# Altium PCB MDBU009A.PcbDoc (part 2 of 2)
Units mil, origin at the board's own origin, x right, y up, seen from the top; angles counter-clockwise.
Board outline 2000 x 3000 mil, 2 copper layers (Top Layer, Bottom Layer), stack 63.4 mil thick; 59 components, 52 nets, 252 pads, 189 vias.
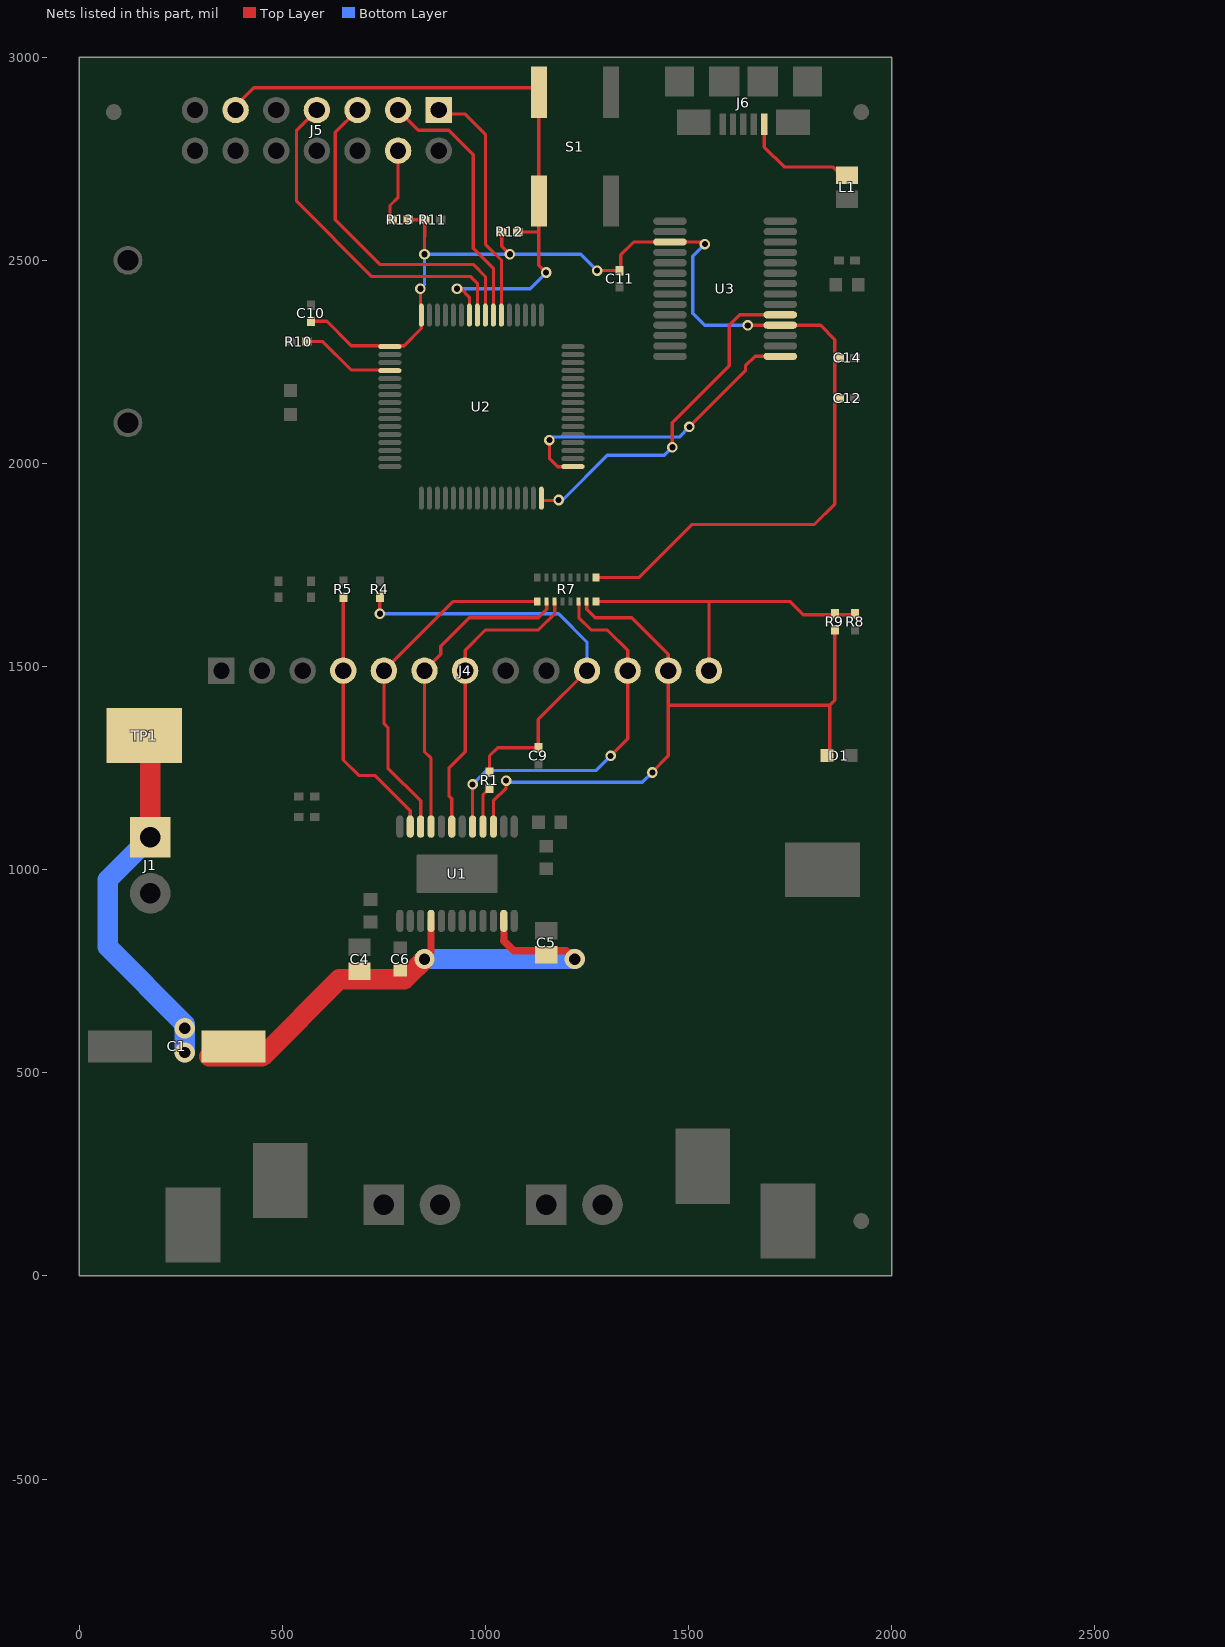
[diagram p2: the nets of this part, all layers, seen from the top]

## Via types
v1: diameter 26, hole 15, Top Layer to Bottom Layer, tented both sides, 177 vias
v2: diameter 19.68, hole 7.87, Top Layer to Bottom Layer, 8 vias
v3: diameter 50, hole 28, Top Layer to Bottom Layer, tented both sides, 4 vias

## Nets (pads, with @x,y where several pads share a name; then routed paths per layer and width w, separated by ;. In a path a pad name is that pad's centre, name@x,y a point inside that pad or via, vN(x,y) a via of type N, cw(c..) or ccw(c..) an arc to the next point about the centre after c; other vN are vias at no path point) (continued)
NetJ5_4: J5.4 R13.2 | length 178.3
  Top Layer w8: R13.2@765,2600 765,2635 785,2655 J5.4@785,2770
NFAULT: D1.2 J4.12 R7.7 R9.1 U1.15 | length 1784
  Top Layer w8: U1.15@1019.57,1102.2 1019.57,1169.57 1050.68,1200.68 v1(1050.68,1219.32) ; R7.7@1249.21,1658.5 1249.21,1640.79 1270,1620 1360,1620 1450,1530 J4.12@1450,1490 1450,1405 ; v1@1410,1240 1450,1280 1450,1405 ; D1.2@1847.8,1279.9 1847.8,1405 ; R9.1@1860,1588.35 1860,1417.2 1847.8,1405 ; 1450,1405 1847.8,1405
  Bottom Layer w8: v1(1050.68,1219.32) 1054.87,1215.13 1386.49,1215.13 v1(1410.68,1239.32)
NSLEEP: J4.11 R7.6 U1.17 | length 953.9
  Top Layer w8: U1.17@968.39,1102.2 v1(968.39,1210) v1@968.39,1218.39 ; R7.6@1230,1658.5 1230,1620 1260,1590 1300,1590 1350,1540 J4.11@1350,1490 1350,1322.1 v1(1307.9,1280)
  Bottom Layer w8: v1(968.39,1210) 1002.39,1244 1040.19,1244 1040.38,1244.19 1060.99,1244.19 1061.18,1244 1271.9,1244 v1(1307.9,1280)
RREF: R1.2 U1.16 | length 104.7
  Top Layer w8: U1.16@993.98,1102.2 993.98,1184.29 R1.2@1010,1200.31
RREF_R: C9.1 J4.10 R1.1 R4.1 | length 1046.1
  Top Layer w8: v1(740,1630) R4.1@740,1670.32 ; R1.1@1010,1241.65 1010,1280 1030,1300 1120,1300 ; C9.1@1130,1299.68 1130,1370 1140,1380 1250,1489.37 J4.10@1250,1490
  Bottom Layer w8: v1(740,1630) 1180,1630 1250,1560 J4.10@1250,1490
RST: J5.11 R12.1 S1.3 S1.4 U2.58 | length 1607.9
  Top Layer w8: J5.11@385,2880 430,2925 1125,2925 1131.42,2931.42 S1.3@1131.42,2913.86 S1.4@1131.42,2646.14 1131.42,2570 ; v1(930,2430) 940,2430 960.47,2409.53 U2.58@960.47,2365.39 ; R12.1@1079.68,2570 1131.42,2570 ; v1(1149.25,2470) 1131.42,2487.83 1131.42,2570
  Bottom Layer w8: v1(930,2430) 1110,2430 v1@1150,2470
RX: U2.32 U3.5 | length 859.5
  Top Layer w8: U2.32@1137.7,1909 v1@1167.38,1909 ; U2.32@1137.7,1929 U2.32@1138.7,1930 ; v1(1460,2040) 1460,2100 1600,2240 1600,2340 1626.02,2366.02 U3.5@1725.83,2366.02
  Bottom Layer w8: v1(1180,1910) 1190,1910 1300,2020 1440,2020 v1(1460,2040)
STATUS: R10.2 U2.4 | length 247.3
  Top Layer w8: R10.2@551.65,2300 600,2300 670,2230 U2.4@770,2230
STEP: J4.7 R7.3 U1.19 | length 745.3
  Top Layer w8: U1.19@917.2,1102.2 917.2,1175.14 910,1182.34 910,1250 950,1290 J4.7@950,1490 950,1540 1000,1590 1130,1590 1170.47,1630.47 R7.3@1170.47,1660.47
TCK: J5.7 U2.57 | length 827
  Top Layer w8: J5.7@585,2870 535,2820 535,2645 720,2460 964,2460 980.1,2443.9 U2.57@980.1,2391
TDI: J5.3 U2.55 | length 620.1
  Top Layer w8: J5.3@785,2870 834.99,2820 910,2820 970,2760 970,2530 1019.5,2480.5 U2.55@1019.5,2391
TDO: J5.1 U2.54 | length 590.9
  Top Layer w8: J5.1@865,2860 950,2860 1000,2810 1000,2539.98 1039.2,2500.78 U2.54@1039.2,2391
TMS: J5.5 U2.56 | length 789.7
  Top Layer w8: J5.5@685,2870 630,2815 630,2600 740,2490 970,2490 999.8,2460.2 U2.56@999.8,2391
TORQUE: J4.4 R5.1 U1.23 | length 657.9
  Top Layer w8: R5.1@650,1668.35 J4.4@650,1490 650,1270 688,1232 728,1232 814.84,1145.16 U1.23@814.84,1102.2
TX: U2.33 U3.1 | length 834
  Top Layer w8: v1(1157.5,2057.5) 1157.5,2012.5 1177.8,1992.2 U2.33@1220.9,1992.2 ; v1(1502,2090) 1640,2228 1640,2240 1663.66,2263.66 U3.1@1725.83,2263.66 ; U3.1@1693.6,2263.6 U3.1@1750,2263.6
  Bottom Layer w8: v1(1157.5,2057.5) 1165,2065 1477,2065 v1(1502,2090)
USM0: J4.6 R7.2 U1.21 | length 789.1
  Top Layer w8: U1.21@866.02,1102.2 866.02,1273.98 850,1290 J4.6@850,1490 890,1530 890,1550 960,1620 1130,1620 1150.79,1640.79 R7.2@1150.79,1660.47
USM1: J4.5 R7.1 U1.22 | length 873.5
  Top Layer w8: U1.22@840.43,1102.2 840.43,1169.57 760,1250 760,1350 750,1360 J4.5@750,1490 920,1660 1127.18,1660 R7.1@1127.66,1660.47
V3P3: C10.1 C11.1 C12.1 C14.1 R7.9 R11.1 R12.2 R13.1 U2.1 U2.64 U3.4 U3.17 | length 3156.9
  Top Layer w8: C10.1@570,2350 610,2350 670,2290 800,2290 842.2,2332.2 842.2,2371 840,2373.2 v1(840,2430) ; R13.1@810,2600 R11.1@850.32,2600 v1(850,2515) ; R12.2@1040.31,2570 1040,2569.69 1040,2535 v1(1060,2515) ; R7.9@1272.34,1719.53 1378.26,1719.53 1508.73,1850 1810,1850 1860,1900 1860,2305 1825,2340 U3.4@1750,2340 ; v1(1275,2474.68) C11.1@1330,2474.68 ; C11.1@1333.32,2478.32 1333.32,2513.32 1365.2,2545.2 1510,2545.2 ; U3.17@1454.17,2545.16 1534.84,2545.16 v1(1540,2540) ; v1@1655,2340 1655.43,2340.43 U3.4@1725.83,2340.43 ; U3.4@1685.4,2340.4 U3.4@1738.9,2340.4
  Bottom Layer w8: v1(840,2430) 850,2440 v1(850,2515) v1(1060,2515) 1234.68,2515 v1(1275,2474.68) ; v1(1540,2540) 1510,2510 1510,2370 1540,2340 v1@1655,2340
  other v1: 1645.72,2340
V3P3R: J4.13 R7.8 R8.2 R9.2 | length 821
  Top Layer w8: R7.8@1272.34,1660 1550,1660 ; J4.13@1550,1490 1550,1660 ; R8.2@1910,1627.72 1782.28,1627.72 1750,1660 1550,1660
VBUS: J6.1 L1.2 | length 293.7
  Top Layer w8: J6.1@1686.18,2840 1686.18,2778.82 1735,2730 1854.56,2730 1875.03,2709.53 L1.2@1890,2709.53
VM: C1.1 C4.2 C5.2 C6.1 J1.1 TP1.1 U1.4 U1.11 | length 2286.3
  Top Layer w17: v3@866.02,796.02 U1.4@866.02,877.8 ; 1045.16,824.84 U1.11@1045.16,873.86
  Top Layer w18: v3(850,780) v3@866.02,796.02 ; 1045.16,824.84 1069.68,800.32 1199.68,800.32 v3(1220,780)
  Top Layer w50: TP1.1@140,1360 175,1325 J1.1@175,1080 ; C1.1@320,540 450,540 640,730 800,730 ; 804.83,734.66 v3(850,780)
  Bottom Layer w50: J1.1@175,1080 70,975 70,810 260,620 v3(260,550) ; v3(850,780) v3(1220,780)
  other v3: 260,610
pads on no net: FID1.1 FID2.1 FID3.1 J5.6 J5.8 J5.10 J5.12 J5.13 J5.14 J6.4 U2.2 U2.3 U2.7 U2.8 U2.9 U2.12 U2.13 U2.14 U2.15 U2.16 U2.17 U2.18 U2.19 U2.20 U2.21 U2.22 U2.27 U2.28 U2.29 U2.30 U2.31 U2.34 U2.35 U2.36 U2.39 U2.40 U2.43 U2.44 U2.45 U2.46 U2.47 U2.48 U2.49 U2.50 U2.51 U2.52 U2.53 U2.59 U2.60 U2.61 U3.2 U3.3 U3.6 U3.8 U3.9 U3.10 U3.11 U3.12 U3.13 U3.14 U3.19 U3.22 U3.23 U3.24 U3.27 U3.28
copper on no net: | length 277.2
  Top Layer w8: 2450,-780 2727.18,-780

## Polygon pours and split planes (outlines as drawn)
GND on Top Layer "Top Layer-GND" (solid, remove dead copper, pour order 12): -4.31,-2.25 -4.31,2997.75 1995.69,2997.75 1995.69,-2.25
GND on Bottom Layer "Bottom Layer-GND" (solid, remove dead copper, pour order 8): 0,-5 0,2995 2000,2995 2000,-5

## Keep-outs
Keep-Out Layer:
  lines w10: -5,-5 2005,-5 2005,3005 -5,3005 -5,-5
  text ".Layer_Name" at 577,-858.49 h60

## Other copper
Top Layer:
  region net GND: 863.77,2332.57 883.47,2332.57 883.47,2302.57 863.77,2302.57
  region net GND: 1140,2290 1198.95,2348.95 1211.05,2348.95 1230,2330 1220,2320 1202.47,2319.14 1195.81,2318.48 1157.32,2280
  region net GND: 790,1960 820,1990 840,1970 810,1940
  region net GND: 1130,830 1070,830 1070,910 1130,910
  region net BOUT1: 1011,807 1011,778 1025,764 1046,785 1028,803 1028,807 1027,808 1012,808
  region net BOUT2: 972,797 972,823 969,826 976,842 1002,816 1002,797
  region net AOUT2: 927,810 927,836 935,844 951,844 952,842 952,822 956,818 957,814 957,810
  region net AOUT1: 885,807 884,826 885,834 899,834 899,833 915,817 915,807
  region net VM: 400,530 470,590 520,640 230,640 230,540 240,520 370,520
  region net GND: 1380,2345 1535,2345 1535,2314.32 1530.68,2310 1380,2310
  text ".Layer_Name" at 577,-858.49 h60
Bottom Layer:
  text ".Layer_Name" at 577,-858.49 h60

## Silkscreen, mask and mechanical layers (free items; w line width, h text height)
Top Overlay:
  circle w10: c740,827.88 r10
  lines w7: 630,670 1280,670 1280,1180 1178.12,1180 630,1180 630,670
  lines w8: 150,1690 460,1690 ; 780,1690 1100,1690 ; 1320,1690 1790,1690
  text "GND" at 70,2560 h40
  text "MCU Reset" at 1095,2515 h30
  text "Status" at 420,2020 h30
  text ".PRJ_Number" at 1430,1820 h40
  text ".PCB_Rev" at 1430,1730 h40
  text "DRV8885EVM" at 1430,1630 h40
  text "VM" at 60,1430 h40
  text "GND" at 340,1410 h30 r270
  text "DVDD" at 440,1410 h30 r270
  text "DECAY_R" at 540,1410 h30 r270
  text "TORQUE" at 640,1410 h30 r270
  text "USM1" at 740,1410 h30 r270
  text "USM0" at 840,1410 h30 r270
  text "STEP" at 935,1410 h30 r270
  text "ENABLE" at 1040,1410 h30 r270
  text "DIR" at 1140,1410 h30 r270
  text "RREF_R" at 1235,1410 h30 r270
  text "nSLEEP" at 1335,1410 h30 r270
  text "nFAULT" at 1440,1410 h30 r270
  text "V3P3R" at 1535,1410 h30 r270
  text "nFAULT" at 1755,1340 h30
  text "VM" at 320,1060 h40
  text "GND" at 320,930 h40
  text "GND" at 1790,820 h40
  text "DRV8885" at 800,610 h40
  text "BOUT1" at 1465,400 h30
  text "AOUT1" at 425,360 h30
  text "AOUT1" at 630,320 h30
  text "AOUT2" at 870,320 h30
  text "BOUT2" at 1030,320 h30
  text "BOUT1" at 1270,320 h30
  text "BOUT2" at 1670,265 h30
  text "AOUT2" at 205,250 h30
  text ".Layer_Name" at 577,-858.49 h60
Bottom Overlay:
  text ".Layer_Name" at 577,-858.49 h60
Top Paste:
  text ".Layer_Name" at 577,-858.49 h60
Bottom Paste:
  text ".Layer_Name" at 577,-858.49 h60
Top Solder:
  text ".Layer_Name" at 577,-858.49 h60
  text ".Layer_Name" at 577,-858.49 h60
Bottom Solder:
  text ".Layer_Name" at 577,-858.49 h60
Drill Guide:
  text ".Layer_Name" at 577,-858.49 h60
M1 Board Outline:
  the board outline again, w10
  text ".Layer_Name" at 577,-858.49 h60
M2 Board Dimensions:
  rectangle: 0,-275 125,-150
  rectangle: 125,-400 500,-275
  lines w7: 0,-275 1000,-275 ; 125,-400 125,-150 ; 250,-400 250,-150 ; 500,-400 500,-150 ; 750,-400 750,-150 ; 0,-400 1000,-400 1000,-150 0,-150 0,-400
  text ".Layer_Name" at 577,-858.49 h60
M3 3D STEP Top:
  text ".Layer_Name" at 577,-858.49 h60
M4 3D STEP Bottom:
  text ".Layer_Name" at 577,-858.49 h60
M5 Assembly Top:
  lines w10: -292,-930.17 6308,-930.17 ; -292,-726.83 6310,-726.83 ; -292,-523.5 -292,-1133.5 3713,-1133.5 6310,-1133.5 6310,-523.5 -291.5,-523.5 -291.5,-1133.5 1284,-1133.5 ; 2173,-1133.5 2173,-523.5 ; 3440,-726.83 3440,-523.5 ; 4280,-726.83 4280,-523.5 ; 4902,-1140 4902,-937.17
  text "COMPONENTS MARKED 'DNP' SHOULD NOT BE POPULATED." at 1153.5,-318.5 h60
  text "ASSEMBLY VARIANT:" at 1153,-434 h60
  text ".VariantName" at 2189,-434 h60
  text "PCB VIEWED FROM TOP SIDE" at -228.5,-655.67 h60
  text "BOARD #:" at 2248,-655.67 h60
  text ".PRJ_Number" at 2793.5,-655.67 h60
  text "REV:" at 3638,-655.67 h60
  text ".PCB_Rev" at 3929.5,-655.67 h60
  text "SVN REV:" at 4476,-655.67 h60
  text ".VersionControl_RevNumber" at 4982,-655.67 h60
  text "TID #:" at 2248,-859 h60
  text ".TID" at 2793.5,-859 h60
  text "PLOT NAME =" at -228.5,-1064.34 h60
  text ".plot_File_Name" at 577,-1064.34 h60
  text "GENERATED    :" at 2250,-1064.34 h60
  text ".Print_Date" at 3119.5,-1064.34 h60
  text ".Print_Time" at 3848.5,-1064.34 h60
  text "TEXAS INSTRUMENTS" at 5113,-1064.34 h60
M6 Assembly Bottom:
  lines w10: -292.5,-727.33 6309.5,-727.33 ; -290.5,-930.67 6309.5,-930.67 ; 1115.5,-1140.5 1115.5,-937.67 ; 1737.5,-727.33 1737.5,-524 ; 2577.5,-727.33 2577.5,-524 ; 3844.5,-1134 3844.5,-524 ; 4733.5,-1134 6309,-1134 6309,-524 -292.5,-524 -292.5,-1134 2304.5,-1134 6309.5,-1134 6309.5,-524
  text "COMPONENTS MARKED 'DNP' SHOULD NOT BE POPULATED." at 6102,-318 h60
  text ".VariantName" at 5058,-434 h60
  text "ASSEMBLY VARIANT:" at 6097,-434 h60
  text ".VersionControl_RevNumber" at 1035.5,-656.17 h60
  text "SVN REV:" at 1541.5,-656.17 h60
  text ".PCB_Rev" at 2088,-656.17 h60
  text "REV:" at 2379.5,-656.17 h60
  text ".PRJ_Number" at 3224,-656.17 h60
  text "BOARD #:" at 3769.5,-656.17 h60
  text "PCB VIEWED FROM BOTTOM SIDE" at 6246,-656.17 h60
  text ".TID" at 3224,-859.5 h60
  text "TID #:" at 3769.5,-859.5 h60
  text "TEXAS INSTRUMENTS" at 904.5,-1064.84 h60
  text ".Print_Time" at 2169,-1064.84 h60
  text ".Print_Date" at 2898,-1064.84 h60
  text "GENERATED    :" at 3767.5,-1064.84 h60
  text ".plot_File_Name" at 5440.5,-1064.84 h60
  text "PLOT NAME =" at 6246,-1064.84 h60
M9 Title Sheet:
  drawing of 57 lines, arcs and shapes, not listed
  text "1" at 739.84,8036.5 h70
  text "2" at 3235.5,8036.5 h70
  text "3" at 5724.84,8036.5 h70
  text "4" at 8231.51,8036.5 h70
  text "5" at 10730.5,8036.5 h70
  text "6" at 13235.5,8036.5 h70
  text "A" at -416.5,6893.5 h70
  text "A" at 14383.5,6893.5 h70
  text "B" at -416.5,4513.5 h70
  text "B" at 14383.5,4513.5 h70
  text "C" at -416.5,2138.5 h70
  text "C" at 14383.5,2138.5 h70
  text "PROJECT TITLE:" at 11343.5,277.5 h45
  text ".PRJ_Title" at 11393.5,144.17 h70
  text "DESIGNED FOR:" at 11343.5,-23.5 h45
  text ".PRJ_Customer" at 11393.5,-163.5 h70
  text "D" at -416.5,-231.5 h70
  text "D" at 14383.5,-231.5 h70
  text "FILE NAME:" at 11343.5,-323.5 h45
  text ".PCB_File_Name_No_Path" at 11393.5,-443.5 h70
  text "Texas Instruments (TI) and/or its licensors do not warrant the accuracy or completeness of this specification" at 6374,-605.34 h45
  text "ENGINEER:" at 11343.5,-613.5 h45
  text "LAYOUT BY:" at 12848.5,-613.5 h45
  text "or any information contained therein. TI and/or its licensors do not warrant that this design will meet" at 6329.01,-718 h45
  text ".PRJ_Engineer" at 11393.5,-768.49 h70
  text ".PCB_Layout" at 12899,-768.49 h70
  text "the specifications, will be suitable for your application or fit for any particular purpose, or will operate in" at 6329.01,-830.67 h45
  text ".Layer_Name" at 577,-858.49 h60
  text "ALTIUM DESIGNER VERSION:" at 12848.5,-923.5 h45
  text "an implementation. TI and/or its licensors do not warrant that the design is production worthy. You should" at 6329.01,-943.33 h45
  text "completely validate and test your design implementation to confirm the system functionality for your application." at 6374,-1056 h45
  text ".print_Scale" at 11393.5,-1056.83 h70
  text ".Application_BuildNumber" at 12899,-1056.83 h70
  text "1" at 739.84,-1263.5 h70
  text "2" at 3235.5,-1263.5 h70
  text "3" at 5724.84,-1263.5 h70
  text "4" at 8231.51,-1263.5 h70
  text "5" at 10730.5,-1263.5 h70
  text "6" at 13235.5,-1263.5 h70
M10 Fab Notes:
  drawing of 185 lines, arcs and shapes, not listed
  text "DESIGN INFORMATION" at 12381.02,5910 h60
  text "MIN. TRACK WIDTH:" at 11736.46,5730 h60
  text "8" at 12832.7,5730 h60
  text "MIL" at 12987.46,5730 h60
  text "MIN. CLEARANCE:" at 11736.46,5598 h60
  text "0.2" at 12772.7,5598 h60
  text "mm" at 12987.46,5598 h60
  text "MIN. VIA PAD SIZE:" at 11736.46,5466 h60
  text "24" at 12802.71,5466 h60
  text "MIL" at 12987.46,5466 h60
  text "0.05mm (2MIL)" at 12431.46,5324.29 h60
  text "MINIMUM ANNULAR RING" at 11407.23,5320 h60
  text "EXTERNAL" at 13139.46,5320 h60
  text "PER" at 11607.23,5202 h60
  text "IPC-D-275 CLASS 2 LEVEL C" at 11827.23,5202 h60
  text "MIL, HOLES" at 13315.46,5089.71 h60
  text "+/-" at 12923,5089 h60
  text "+/-" at 13777,5089 h60
  text "REGISTRATION TOLERANCES:" at 11407.23,5084 h60
  text "METAL" at 12607,5084 h60
  text "5" at 13183.2,5084 h60
  text "3" at 14016.2,5084 h60
  text "MIL" at 14132.46,5084 h60
  text "MATERIAL:" at 11332.46,4874.54 h60
  text "FR-4 High Tg" at 12318.9,4734.21 h60
  text "FR-408" at 11753.46,4725.64 h60
  text "X" at 12165.46,4725.64 h60
  text "OTHER" at 13241.46,4725.64 h60
  text "62 MIL (1.6mm) +/-10%" at 12073.56,4562.92 h60
  text "THICKNESS:" at 11407.23,4558.64 h60
  text "X" at 11945.4,4558.64 h60
  text "OTHER" at 13358.46,4558.64 h60
  text "TOLERANCE:" at 11407.23,4400.64 h60
  text "X" at 12246.53,4400.64 h60
  text "ANSI IPC-6012 TYPE 3 CLASS 2" at 12433.48,4400.64 h60
  text "OTHER +/-" at 12433.46,4244.64 h60
  text "BOW & TWIST:" at 11407.23,4087.64 h60
  text "X" at 12246.53,4087.64 h60
  text "ANSI IPC-6012 TYPE 3 CLASS 2" at 12433.48,4087.64 h60
  text "OTHER +/-" at 12433.46,3929.13 h60
  text "DRILLING:" at 11332.46,3790.64 h60
  text "REFERENCE:" at 11407.23,3673.64 h60
  text "X" at 12055.46,3673.64 h60
  text "AS SHOWN" at 12242.46,3673.64 h60
  text "X" at 12956.46,3673.64 h60
  text "NC_DRILL FILES" at 13093.46,3673.64 h60
  text "PTH MIN COPPER THICKNESS:" at 11407.23,3515.64 h60
  text "X" at 12757.46,3515.64 h60
  text "1MIL" at 12894.46,3515.64 h60
  text "OTHER" at 13391.46,3515.64 h60
  text "BOARD FINISH:" at 11332.46,3356.64 h60
  text "SILKSCREEN:" at 11487.68,3238.64 h60
  text "X" at 12436.46,3238.64 h60
  text "TOP" at 12562.46,3238.64 h60
  text "X" at 12946.46,3238.64 h60
  text "BOTTOM" at 13073.46,3238.64 h60
  text "SILKSCREEN COLOR:" at 11487.68,3071.64 h60
  text "X" at 12435.42,3071.64 h60
  text "WHITE" at 12562.46,3071.64 h60
  text "OTHER" at 13073.46,3071.64 h60
  text "SOLDER RESIST COLOR:" at 11487.68,2901.64 h60
  text "X" at 12055.42,2742.44 h60
  text "GREEN" at 12182.46,2742.44 h60
  text "BLUE" at 12773.46,2742.44 h60
  text "OTHER" at 13311.46,2742.44 h60
  text "IMMERSION GOLD (ENIG)" at 12393.46,2553.92 h60
  text "ENEPIG" at 13731,2550.64 h60
  text "SURFACE FINISH:" at 11332.46,2549.64 h60
  text "X" at 12206.51,2549.64 h60
  text "IMM. TIN/SILVER OR EQUIV" at 11662,2392.64 h60
  text "OTHER" at 13093.46,2392.64 h60
  text "ARRAY/PANEL:" at 11332.46,2213.64 h60
  text "CUT AND TRIM PER MECH LAYER 1" at 12393.46,2209.35 h60
  text "N.C. ROUTE" at 12393.46,2057.64 h60
  text "X" at 13072.46,2057.64 h60
  text "V. SCORE" at 13259.46,2057.64 h60
  text "CERTIFICATION:" at 11332.46,1920.64 h60
  text "MATERIALS AND WORKMANSHIP FOR ALL PCBS" at 12057.46,1920.64 h60
  text "TO MEET OR EXCEED THE REQUIREMENTS OF:" at 12057.46,1822.64 h60
  text "X" at 11683.96,1686.13 h60
  text "ANSI IPC-A-600F CLASS ->" at 11822.96,1686.13 h60
  text "X" at 13462.02,1686.13 h60
  text "2" at 13580.96,1686.14 h60
  text "1" at 13265.96,1684.64 h60
  text "3" at 13934.96,1684.64 h60
  text "X" at 11686.02,1526.64 h60
  text "UL 94V-0" at 11822.96,1526.64 h60
  text "X" at 12498.02,1526.64 h60
  text "RoHS" at 12634.96,1526.64 h60
  text "OTHER" at 13279.36,1526.64 h60
  text "PER ORDER" at 13676.42,1526.64 h60
  text "ADDITIONAL REQUIREMENTS:" at 11332.46,1385.64 h60
  text "MICROSECTION:" at 11407.23,1270.64 h60
  text "YES" at 12312.96,1270.64 h60
  text "REQUIRED" at 13174.46,1114.49 h60
  text "BARE BOARD ELEC. TEST:" at 11407.23,1111.64 h60
  text "NONE" at 12712.96,1111.64 h60
  text "X" at 13047.46,1111.64 h60
  text "PER ORDER" at 13766.46,1111.64 h60
  text "MANUFACTURER'S UL:" at 11407.23,954.64 h60
  text "RAIL" at 12572.96,950.35 h60
  text "METAL" at 13064.77,950.35 h60
  text "X" at 13440,950 h60
  text "SILK" at 13576.46,950.35 h60
  text ".Layer_Name" at 577,-858.49 h60
M11 Gerber Information:
  lines w10: -292,-930.17 6308,-930.17 ; -292,-726.83 6310,-726.83 ; -292,-523.5 -292,-1133.5 3713,-1133.5 6310,-1133.5 6310,-523.5 -291.5,-523.5 -291.5,-1133.5 1284,-1133.5 ; 2173,-1133.5 2173,-523.5 ; 3440,-726.83 3440,-523.5 ; 4280,-726.83 4280,-523.5 ; 4902,-1140 4902,-937.17
  text "ALL ARTWORK VIEWED FROM TOP SIDE" at -228.5,-655.67 h60
  text "BOARD #:" at 2248,-655.67 h60
  text ".PRJ_Number" at 2793.5,-655.67 h60
  text "REV:" at 3638,-655.67 h60
  text ".PCB_Rev" at 3929.5,-655.67 h60
  text "SVN REV:" at 4476,-655.67 h60
  text ".VersionControl_RevNumber" at 4982,-655.67 h60
  text "LAYER NAME =" at -228.5,-858.49 h60
  text "TID #:" at 2248,-859 h60
  text ".TID" at 2793.5,-859 h60
  text "PLOT NAME =" at -228.5,-1064.34 h60
  text ".plot_File_Name" at 577,-1064.34 h60
  text "GENERATED    :" at 2250,-1064.34 h60
  text ".Print_Date" at 3119.5,-1064.34 h60
  text ".Print_Time" at 3848.5,-1064.34 h60
  text "TEXAS INSTRUMENTS" at 5113,-1064.34 h60
M12 Stackup:
  drawing of 165 lines, arcs and shapes, not listed
  text "Layer" at 9790,7830 h60
  text "Name" at 10199.91,7830 h60
  text "Material" at 11059.68,7830 h60
  text "Thickness" at 11919.45,7830 h60
  text "Constant" at 12569.28,7830 h60
  text "Board Layer Stack" at 13139.14,7830 h60
  text "1" at 9790,7710 h60
  text "Top Overlay" at 10199.91,7710 h60
  text "2" at 9790,7590 h60
  text "Top Solder" at 10199.91,7590 h60
  text "Solder Resist" at 11059.68,7590 h60
  text "0.40mil" at 11919.45,7590 h60
  text "3.5" at 12569.28,7590 h60
  text "3" at 9790,7470 h60
  text "Top Layer" at 10199.91,7470 h60
  text "Copper" at 11059.68,7470 h60
  text "2.10mil" at 11919.45,7470 h60
  text "4" at 9790,7350 h60
  text "Dielectric1" at 10199.91,7350 h60
  text "FR-4" at 11059.68,7350 h60
  text "59.20mil" at 11919.45,7350 h60
  text "4.8" at 12569.28,7350 h60
  text "5" at 9790,7230 h60
  text "Bottom Layer" at 10199.91,7230 h60
  text "Copper" at 11059.68,7230 h60
  text "2.10mil" at 11919.45,7230 h60
  text "6" at 9790,7110 h60
  text "Bottom Solder" at 10199.91,7110 h60
  text "Solder Resist" at 11059.68,7110 h60
  text "0.40mil" at 11919.45,7110 h60
  text "3.5" at 12569.28,7110 h60
  text ".Layer_Name" at 577,-858.49 h60
M13 Component Bodies Top:
  text ".Layer_Name" at 577,-858.49 h60
M14 Component Bodies Bottom:
  text ".Layer_Name" at 577,-858.49 h60
M15 Courtyards Top:
  text ".Layer_Name" at 577,-858.49 h60
M16 Courtyards Bottom:
  text ".Layer_Name" at 577,-858.49 h60
Drill Drawing:
  circle w1: c2592.8,2770.83 r24.91
  lines w1: 2567.89,2023.54 2592.8,1998.63 2617.71,2023.54 2592.8,2048.45 2567.89,2023.54 ; 2567.89,2148.09 2567.89,2160.54 2580.35,2173 2567.89,2185.45 2567.89,2197.91 2580.35,2197.91 2592.8,2185.45 2605.26,2197.91 2617.71,2197.91 2617.71,2185.45 2605.26,2173 2617.71,2160.54 2617.71,2148.09 2605.26,2148.09 2592.8,2160.54 2580.35,2148.09 2567.89,2148.09 ; 2567.89,2310 2580.35,2310 2580.35,2297.54 2605.26,2297.54 2605.26,2310 2617.71,2310 2617.71,2334.91 2605.26,2334.91 2605.26,2347.36 2580.35,2347.36 2580.35,2334.91 2567.89,2334.91 2567.89,2310 ; 2567.89,2459.46 2580.35,2459.46 2592.8,2447 2605.26,2459.46 2617.71,2459.46 2605.26,2471.91 2617.71,2484.37 2605.26,2484.37 2592.8,2496.82 2580.35,2484.37 2567.89,2484.37 2580.35,2471.91 2567.89,2459.46 ; 2567.89,2646.28 2617.71,2646.28 2592.8,2596.46 2567.89,2646.28
  lines w12: 2500,1953.79 4619.4,1953.79 ; 2500,2850.54 4619.4,2850.54 ; 2870.67,1804.33 2870.67,3000 ; 3227.78,1804.33 3227.78,3000 ; 3889.79,1804.33 3889.79,3000 ; 4174.14,1804.33 4174.14,3000 ; 2500,1804.33 4619.4,1804.33 4619.4,3000 2500,3000 2500,1804.33
  text "Symbol" at 2589.68,2895.38 h72
  text "Quantity" at 2915.51,2895.38 h72
  text "Finished Hole Size" at 3272.62,2895.38 h72
  text "Plated" at 3934.62,2895.38 h72
  text "Hole Type" at 4218.98,2895.38 h72
  text "8" at 2915.51,2745.92 h60
  text "7.87mil (0.200mm)" at 3272.62,2745.92 h60
  text "PTH" at 3934.62,2745.92 h60
  text "Round" at 4218.98,2745.92 h60
  text "177" at 2915.51,2596.46 h60
  text "15.00mil (0.381mm)" at 3272.62,2596.46 h60
  text "PTH" at 3934.62,2596.46 h60
  text "Round" at 4218.98,2596.46 h60
  text "4" at 2915.51,2447 h60
  text "28.00mil (0.711mm)" at 3272.62,2447 h60
  text "PTH" at 3934.62,2447 h60
  text "Round" at 4218.98,2447 h60
  text "27" at 2915.51,2297.54 h60
  text "40.00mil (1.016mm)" at 3272.62,2297.54 h60
  text "PTH" at 3934.62,2297.54 h60
  text "Round" at 4218.98,2297.54 h60
  text "6" at 2915.51,2148.09 h60
  text "50.00mil (1.270mm)" at 3272.62,2148.09 h60
  text "PTH" at 3934.62,2148.09 h60
  text "Round" at 4218.98,2148.09 h60
  text "2" at 2915.51,1998.63 h60
  text "51.18mil (1.300mm)" at 3272.62,1998.63 h60
  text "PTH" at 3934.62,1998.63 h60
  text "Round" at 4218.98,1998.63 h60
  text "224 Total" at 2915.51,1849.17 h60
  text ".Layer_Name" at 577,-858.49 h60

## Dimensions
0,0 to 0,3000 on M2 Board Dimensions
0,0 to 2000,0 on M2 Board Dimensions
0,-400 to 1000,-400 on M2 Board Dimensions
